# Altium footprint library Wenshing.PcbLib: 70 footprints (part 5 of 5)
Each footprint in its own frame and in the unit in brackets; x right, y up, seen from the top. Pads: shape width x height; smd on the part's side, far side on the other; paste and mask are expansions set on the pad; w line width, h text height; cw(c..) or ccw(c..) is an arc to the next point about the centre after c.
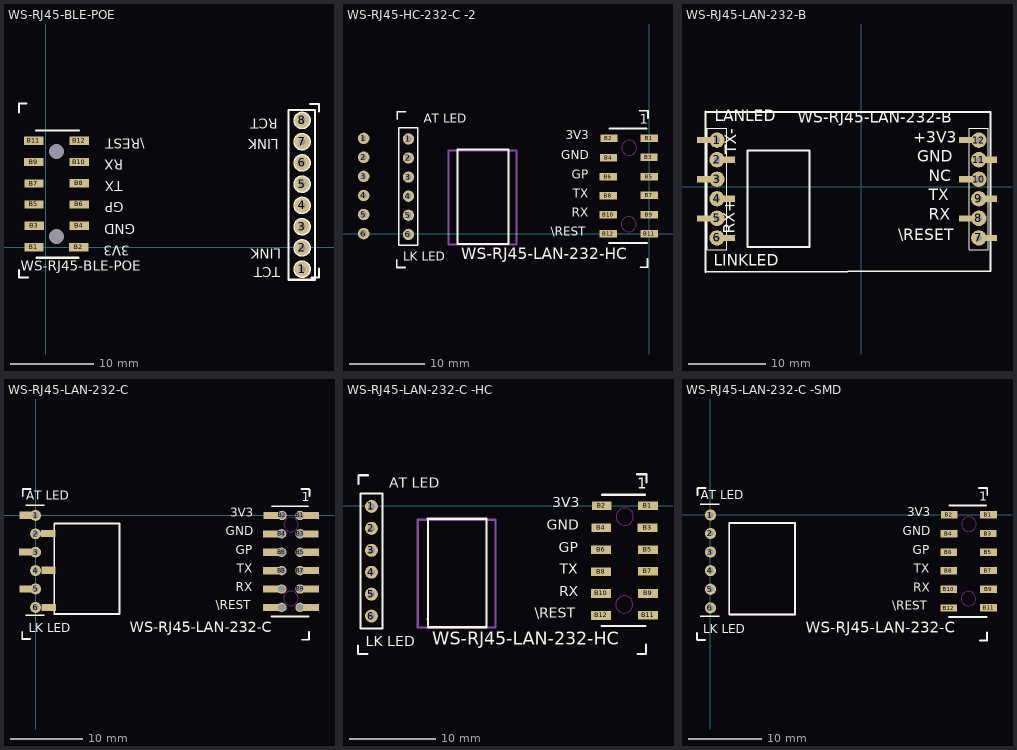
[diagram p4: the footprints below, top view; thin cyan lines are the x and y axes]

## WS-RJ45-BLE-POE [mm]
pads (23):
  round 0 hole 1.8: 0(1.241,1.272)
  round 0 hole 1.8 mask+0.102: 0(1.241,11.432)
  round 1 on Top Overlay mask+0.102: 0(1.29,6.375)
  round 1.8 hole 0.75 mask-0.3: 1(30.624,-2.635) 2(30.624,-0.095) 3(30.624,2.445) 4(30.624,4.985) 5(30.624,7.525) 6(30.624,10.065) 7(30.624,12.605) 8(30.624,15.145)
  rect 2.3x1 smd mask+0.102: B1(-1.435,0) B2(3.915,0) B3(-1.41,2.55) B4(3.965,2.575) B5(-1.435,5.1) B6(3.99,5.1) B7(-1.435,7.6) B8(3.99,7.65) B9(-1.46,10.175) B10(3.99,10.175) B11(-1.46,12.7) B12(3.99,12.725)
Top Overlay:
  circle w0.5: c30.624,-2.635 r0.8
  circle w0.5: c30.624,2.445 r0.8
  circle w0.5: c30.624,4.985 r0.8
  circle w0.5: c30.624,-0.095 r0.8
  circle w0.5: c30.624,15.145 r0.8
  circle w0.5: c30.624,7.525 r0.8
  circle w0.5: c30.624,10.065 r0.8
  circle w0.5: c30.624,12.605 r0.8
  lines w0.254: -3.226,-2.743 -3.226,-3.632 -2.159,-3.632 ; -3.226,16.104 -3.226,17.17 -2.337,17.17 ; -1.16,13.95 3.94,13.95 ; -1.11,-1.275 3.865,-1.275 ; 31.572,17.12 32.639,17.12 32.639,16.231 ; 31.75,-3.632 32.639,-3.632 32.639,-2.565 ; 28.973,-3.905 32.148,-3.905 32.148,16.415 28.973,16.415 28.973,-3.905
  text "LINK" at 28.143,0.254 h2.03
  text "RCT" at 27.737,15.773 h2.03
  text "WS-RJ45-BLE-POE" at -2.997,-3.251 h1.98
  text "TCT" at 28.016,-1.981 h2.03
  text "LINK" at 27.838,13.335 h2.03
  text "\REST" at 11.819,13.346 h2.03
  text "RX" at 9.246,10.878 h2.03
  text "TX" at 9.152,8.317 h2.03
  text "GP" at 9.279,5.777 h2.03
  text "GND" at 10.657,3.181 h2.03
  text "3V3" at 10.041,0.57 h2.03
Bottom Overlay:
  lines w0.254: 29.608,-3.905 31.513,-3.905 ; 29.608,-1.365 31.513,-1.365 ; 29.608,1.175 31.513,1.175 ; 29.608,3.715 31.513,3.715 ; 29.608,6.255 31.513,6.255 ; 29.608,8.795 31.513,8.795 ; 29.608,11.335 31.513,11.335 ; 29.608,16.415 31.513,16.415 ; 29.608,13.875 31.513,13.875 29.608,13.875
3D body "Connector 12-pin 2.54mm SMT.stp": height 6, standoff -0.2, extent -2.468,-1.299 5.182,13.741

## WS-RJ45-HC-232-C -2 [mm]
pads (25):
  round 1.524 hole 0.8 mask+0.102: 1(-38,12.675) 2(-38,10.16) 3(-38,7.62) 4(-38,5.08) 5(-38,2.54) 6(-38,0)
  round 1.5 hole 0.8 mask+0.102: 1(-32.058,12.608) 2(-32.058,10.068) 3(-32.058,7.528) 4(-32.058,4.988) 5(-32.058,2.448) 6(-32.058,-0.092)
  rect 0.2x0.2 on Bottom Overlay: 2(-32.058,6.308)
  rect 2.3x1 smd mask+0.102: B1(-0.025,12.7) B2(-5.375,12.7) B3(-0.05,10.15) B4(-5.425,10.125) B5(-0.025,7.6) B6(-5.45,7.6) B7(-0.025,5.1) B8(-5.45,5.05) B9(0,2.525) B10(-5.45,2.525) B11(0,0) B12(-5.45,-0.025)
Top Overlay:
  lines w0.203: -33.328,-1.524 -33.328,14.097 -30.788,14.097 -30.788,-1.524 -33.328,-1.524
  lines w0.254: -33.612,-3.527 -33.612,-4.475 -33.585,-4.502 -32.512,-4.502 ; -33.537,15.248 -33.537,16.196 -33.51,16.223 -32.437,16.223 ; -25.554,11.176 -18.749,11.176 ; -25.523,-0.462 -25.518,-0.457 -25.513,-0.457 ; -25.513,11.176 -25.513,-0.457 ; -18.718,11.176 -18.718,-1.397 -25.173,-1.397 -25.471,-1.397 -25.513,-1.356 -25.513,-0.457 ; -5.4,-1.25 -0.3,-1.25 ; -5.325,13.975 -0.35,13.975 ; -1.285,16.35 -0.212,16.35 -0.185,16.323 -0.185,15.375 ; -1.21,-4.475 -0.262,-4.475 -0.235,-4.448 -0.235,-3.375
  text "WS-RJ45-LAN-232-HC" at -25,-3.92 h2.54
  text "\REST" at -13.141,-0.697 h2.03
  text "RX" at -10.315,1.822 h2.03
  text "TX" at -10.22,4.383 h2.03
  text "GP" at -10.347,6.923 h2.03
  text "GND" at -11.725,9.519 h2.03
  text "3V3" at -11.109,12.13 h2.03
  text "AT LED" at -29.999,14.351 h2.03
  text "LK LED" at -32.743,-3.999 h2.03
  text "1" at -1.25,14.65 h1.27
Keep-Out Layer:
  circle w0.051: c-2.7,11.425 r1
  circle w0.051: c-2.75,1.25 r1
Mechanical 13:
  lines w0.254: -26.697,-1.422 -17.68,-1.422 -17.68,11.074 -26.621,11.074 -26.697,11.074 -26.697,-1.422
3D body "Copy of RJ45 HC多IO.step": height 9.59, standoff -1.95, extent -33.682,-4.533 2.055,16.217
3D body "Connector 12-pin 2.54mm SMT.stp": height 6.5, standoff 0.3, extent -6.75,-1.09 0.9,13.95
3D body: height 3.55, standoff 0, extent -33.3,-1.666 -30.801,14.073

## WS-RJ45-LAN-232-B [mm]
pads (48):
  rect 0.2x0.2 on Top Overlay: 0(-18.729,-6.625) 0(-18.729,-4.085) 0(-18.729,-1.545) 0(-18.729,0.995) 0(-18.729,3.535) 0(-18.729,6.075) 0(15.271,-6.625) 0(15.271,-4.085) 0(15.271,-1.545) 0(15.271,0.995) 0(15.271,3.535) 0(15.271,6.075) 1(-18.729,-0.275) 1(-18.729,-4.085) 1(-18.729,-1.545) 1(-18.729,0.995) 1(-18.729,3.535) 1(-18.729,6.075) 1(15.271,-0.275) 1(15.271,-4.085) 1(15.271,-1.545) 1(15.271,0.995) 1(15.271,3.535) 1(15.271,6.075)
  rect 2x0.8 smd: 1(-20.329,6.075) 3(-20.329,0.995) 5(-20.329,-4.085) 8(13.671,-4.085) 10(13.671,0.995) 12(13.671,6.075)
  round 2 hole 0.8 mask+0.102: 1(-18.729,6.075) 2(-18.729,3.535) 3(-18.729,0.995) 4(-18.729,-1.545) 5(-18.729,-4.085) 6(-18.729,-6.625) 7(15.271,-6.625) 8(15.271,-4.085) 9(15.271,-1.545) 10(15.271,0.995) 11(15.271,3.535) 12(15.271,6.075)
  rect 1.7x0.8 smd: 2(-17.225,3.535) 4(-17.225,-1.545) 6(-17.225,-6.625) 7(16.775,-6.625) 9(16.775,-1.545) 11(16.775,3.535)
Top Overlay:
  lines w0.1: -19.979,7.595 -18.729,7.595 -17.479,7.595 ; -19.979,7.595 -19.979,-8.145 -18.729,-8.145 -17.479,-8.145 -17.479,-0.275 -17.479,7.595 ; -19.979,7.595 -19.129,7.595 -17.479,7.595 ; 14.021,7.595 15.271,7.595 16.521,7.595 ; 14.021,7.595 14.021,-8.145 15.271,-8.145 16.521,-8.145 16.521,-0.275 16.521,7.595 ; 14.021,7.595 14.871,7.595 16.521,7.595
  lines w0.254: -20.254,9.75 16.746,9.75 ; -20.229,9.8 -20.229,-11.071 16.771,-10.921 16.771,9.7 ; -14.775,-7.775 -6.729,-7.775 -6.729,4.725 -14.775,4.725 -14.775,-7.775
  text "WS-RJ45-LAN-232-B" at -8.225,7.825 h2.54
  text "+3V3" at 6.771,5.225 h2.5
  text "GND" at 7.271,2.725 h2.5
  text "NC" at 8.771,0.225 h2.5
  text "TX" at 8.771,-2.275 h2.5
  text "RX" at 8.771,-4.775 h2.5
  text "\RESET" at 4.771,-7.475 h2.5
  text "LINKLED" at -19.129,-10.759 h2.5
  text "RX+" at -15.911,-6.06 h2.5
  text "TX-" at -15.729,4.225 h2.5
  text "LANLED" at -19.05,8.025 h2.5
Bottom Solder:
  circle w0.8: c15.271,6.075 r0.4
  circle w0.8: c15.246,3.525 r0.4
  circle w0.8: c15.296,1 r0.4
  circle w0.8: c15.271,-1.55 r0.4
  circle w0.8: c15.246,-4.075 r0.4
  circle w0.8: c15.271,-6.6 r0.4
  circle w0.8: c-18.729,6.075 r0.4
  circle w0.8: c-18.729,3.525 r0.4
  circle w0.8: c-18.729,1.025 r0.4
  circle w0.8: c-18.729,-1.575 r0.4
  circle w0.8: c-18.729,-4.1 r0.4
  circle w0.8: c-18.729,-6.6 r0.4
Mechanical 10:
  lines w0.1: -19.129,-7.025 -18.329,-7.025 -18.329,-6.225 -19.129,-6.225 -19.129,-7.025 ; -19.129,-4.485 -18.329,-4.485 -18.329,-3.685 -19.129,-3.685 -19.129,-4.485 ; -19.129,-1.945 -18.329,-1.945 -18.329,-1.145 -19.129,-1.145 -19.129,-1.945 ; -19.129,0.595 -18.329,0.595 -18.329,1.395 -19.129,1.395 -19.129,0.595 ; -19.129,3.135 -18.329,3.135 -18.329,3.935 -19.129,3.935 -19.129,3.135 ; -19.129,5.675 -18.329,5.675 -18.329,6.475 -19.129,6.475 -19.129,5.675 ; 14.871,-7.025 15.671,-7.025 15.671,-6.225 14.871,-6.225 14.871,-7.025 ; 14.871,-4.485 15.671,-4.485 15.671,-3.685 14.871,-3.685 14.871,-4.485 ; 14.871,-1.945 15.671,-1.945 15.671,-1.145 14.871,-1.145 14.871,-1.945 ; 14.871,0.595 15.671,0.595 15.671,1.395 14.871,1.395 14.871,0.595 ; 14.871,3.135 15.671,3.135 15.671,3.935 14.871,3.935 14.871,3.135 ; 14.871,5.675 15.671,5.675 15.671,6.475 14.871,6.475 14.871,5.675
3D body: height 0.2, standoff 0, extent -17.499,3.135 -16.6,3.935
3D body: height 0.2, standoff 0, extent -17.499,-1.945 -16.6,-1.145
3D body: height 0.2, standoff 0, extent -17.499,-7.025 -16.6,-6.225
3D body: height 0.2, standoff 0, extent -20.859,5.675 -19.959,6.475
3D body: height 0.2, standoff 0, extent -20.859,0.595 -19.959,1.395
3D body: height 0.2, standoff 0, extent -20.859,-4.485 -19.959,-3.685
3D body: height 0.3, standoff 0, extent -19.129,5.676 -18.33,6.474
3D body: height 0.3, standoff 0, extent -19.129,3.136 -18.33,3.934
3D body: height 0.3, standoff 0, extent -19.129,0.596 -18.33,1.394
3D body: height 0.3, standoff 0, extent -19.129,-1.944 -18.33,-1.146
3D body: height 0.3, standoff 0, extent -19.129,-4.484 -18.33,-3.686
3D body: height 0.3, standoff 0, extent -19.129,-7.024 -18.33,-6.226
3D body: height 3.55, standoff 0, extent -19.979,-8.144 -17.48,7.594
3D body: height 0.2, standoff 0, extent 16.501,3.135 17.4,3.935
3D body: height 0.2, standoff 0, extent 16.501,-1.945 17.4,-1.145
3D body: height 0.2, standoff 0, extent 16.501,-7.025 17.4,-6.225
3D body: height 0.2, standoff 0, extent 14.812,5.351 15.712,6.151
3D body: height 0.2, standoff 0, extent 14.558,0.525 15.458,1.325
3D body: height 0.2, standoff 0, extent 14.685,-4.682 15.585,-3.882
3D body: height 0.3, standoff 0, extent 14.871,5.676 15.67,6.474
3D body: height 0.3, standoff 0, extent 14.871,3.136 15.67,3.934
3D body: height 0.3, standoff 0, extent 14.871,0.596 15.67,1.394
3D body: height 0.3, standoff 0, extent 14.871,-1.944 15.67,-1.146
3D body: height 0.3, standoff 0, extent 14.871,-4.484 15.67,-3.686
3D body: height 0.3, standoff 0, extent 14.871,-7.024 15.67,-6.226
3D body: height 3.55, standoff 0, extent 14.021,-8.144 16.52,7.594
3D body "TRW-TCP232.step": height 9.09, standoff -2.45, extent -20.426,-11 16.826,9.75

## WS-RJ45-LAN-232-C [mm]
pads (38):
  round 1 on Top Overlay mask+0.102: 0(-0.025,-6.35) 0(35.25,-6.375)
  rect 2x1 smd mask+0.102: 1(-1.21,0.025) 2(1.765,-2.5) 3(-1.285,-5.05) 4(1.79,-7.575) 5(-1.21,-10.15) 6(1.815,-12.7)
  round 1.5 hole 0.8 mask+0.102: 1(0,0) 2(0,-2.54) 3(0,-5.08) 4(0,-7.62) 5(0,-10.16) 6(0,-12.7)
  round 1.3 hole 1 mask+0.102: B1(36.54,0) B2(34.04,0) B3(36.54,-2.54) B4(34,-2.54) B5(36.54,-5.08) B6(34,-5.08) B7(36.54,-7.62) B8(34,-7.62) B9(36.54,-10.16) B10(34,-10.16) B11(36.54,-12.7) B12(34,-12.7)
  rect 2.3x1 smd mask+0.102: B1(37.975,0) B2(32.625,0) B3(37.95,-2.55) B4(32.575,-2.575) B5(37.975,-5.1) B6(32.55,-5.1) B7(37.975,-7.6) B8(32.55,-7.65) B9(38,-10.175) B10(32.55,-10.175) B11(38,-12.7) B12(32.55,-12.725)
Top Layer:
  lines w0.305: 0,-10.16 0.045,-10.115 ; 0,-7.62 0.229,-7.849
Top Overlay:
  lines w0.203: -1.365,-13.82 1.175,-13.82 ; -1.365,1.42 1.175,1.42
  lines w0.254: -1.835,-16.1 -1.835,-17.048 -1.808,-17.075 -0.735,-17.075 ; -1.76,2.675 -1.76,3.623 -1.733,3.65 -0.66,3.65 ; 32.6,-13.95 37.7,-13.95 ; 32.675,1.275 37.65,1.275 ; 36.715,3.65 37.788,3.65 37.815,3.623 37.815,2.675 ; 36.79,-17.175 37.738,-17.175 37.765,-17.148 37.765,-16.075 ; 2.575,-13.595 11.575,-13.595 11.575,-1.095 2.575,-1.095 2.575,-13.595
  text "1" at 36.75,1.95 h1.27
  text "LK LED" at -0.966,-16.572 h2.03
  text "AT LED" at -1.31,1.725 h2.03
  text "3V3" at 26.891,-0.57 h2.03
  text "GND" at 26.275,-3.181 h2.03
  text "GP" at 27.653,-5.777 h2.03
  text "TX" at 27.78,-8.317 h2.03
  text "RX" at 27.685,-10.878 h2.03
  text "\REST" at 24.859,-13.397 h2.03
  text "WS-RJ45-LAN-232-C" at 13,-16.62 h2.54
Bottom Overlay:
  circle w0.4: c34.05,0 r1.2
  circle w0.4: c36.54,0 r1.2
  circle w0.4: c36.54,-2.54 r1.2
  circle w0.4: c34,-2.54 r1.2
  circle w0.4: c34,-5.08 r1.2
  circle w0.4: c36.54,-5.08 r1.2
  circle w0.4: c36.54,-7.62 r1.2
  circle w0.4: c34,-7.62 r1.2
  circle w0.4: c36.54,-10.16 r1.2
  circle w0.4: c34,-10.16 r1.2
  circle w0.4: c34,-12.7 r1.2
  circle w0.4: c36.54,-12.7 r1.2
  circle w0.4: c0,0 r1.2
  circle w0.4: c0,-2.54 r1.2
  circle w0.4: c0,-5.08 r1.2
  circle w0.4: c0,-7.62 r1.2
  circle w0.4: c0,-10.16 r1.2
  circle w0.4: c0,-12.7 r1.2
Keep-Out Layer:
  circle w0.051: c35.25,-11.45 r1
  circle w0.051: c35.3,-1.275 r1
3D body "Connector 12-pin 2.54mm SMT.stp": height 6.5, standoff 0.3, extent 31.25,-13.79 38.9,1.25
3D body "RJ45 LNA多IO.step": height 9.27, standoff -2.95, extent -1.799,-17.375 37.749,3.375
3D body: height 3.55, standoff 0, extent -1.199,-13.844 1.299,1.894

## WS-RJ45-LAN-232-C -HC [mm]
pads (19):
  round 1.5 hole 0.8 mask+0.102: 1(5.942,-0.092) 2(5.942,-2.632) 3(5.942,-5.172) 4(5.942,-7.712) 5(5.942,-10.252) 6(5.942,-12.792)
  rect 0.2x0.2 on Bottom Overlay: 2(5.942,-6.392)
  rect 2.3x1 smd mask+0.102: B1(37.975,0) B2(32.625,0) B3(37.95,-2.55) B4(32.575,-2.575) B5(37.975,-5.1) B6(32.55,-5.1) B7(37.975,-7.6) B8(32.55,-7.65) B9(38,-10.175) B10(32.55,-10.175) B11(38,-12.7) B12(32.55,-12.725)
Top Overlay:
  lines w0.203: 4.672,-14.224 4.672,1.397 7.212,1.397 7.212,-14.224 4.672,-14.224
  lines w0.254: 4.388,-16.227 4.388,-17.175 4.415,-17.202 5.488,-17.202 ; 4.463,2.548 4.463,3.496 4.49,3.523 5.563,3.523 ; 12.446,-1.524 19.251,-1.524 ; 12.477,-13.162 12.482,-13.157 12.487,-13.157 ; 12.487,-1.524 12.487,-13.157 ; 19.282,-1.524 19.282,-14.097 12.827,-14.097 12.529,-14.097 12.487,-14.056 12.487,-13.157 ; 32.6,-13.95 37.7,-13.95 ; 32.675,1.275 37.65,1.275 ; 36.715,3.65 37.788,3.65 37.815,3.623 37.815,2.675 ; 36.79,-17.175 37.738,-17.175 37.765,-17.148 37.765,-16.075
  text "WS-RJ45-LAN-232-HC" at 13,-16.62 h2.54
  text "\REST" at 24.859,-13.397 h2.03
  text "RX" at 27.685,-10.878 h2.03
  text "TX" at 27.78,-8.317 h2.03
  text "GP" at 27.653,-5.777 h2.03
  text "GND" at 26.275,-3.181 h2.03
  text "3V3" at 26.891,-0.57 h2.03
  text "AT LED" at 8.001,1.651 h2.03
  text "LK LED" at 5.257,-16.699 h2.03
  text "1" at 36.75,1.95 h1.27
Keep-Out Layer:
  circle w0.051: c35.3,-1.275 r1
  circle w0.051: c35.25,-11.45 r1
Mechanical 13:
  lines w0.254: 11.303,-14.122 20.32,-14.122 20.32,-1.626 11.379,-1.626 11.303,-1.626 11.303,-14.122
3D body "Copy of RJ45 HC多IO.step": height 9.59, standoff -1.95, extent 4.318,-17.233 40.055,3.517
3D body "Connector 12-pin 2.54mm SMT.stp": height 6.5, standoff 0.3, extent 31.25,-13.79 38.9,1.25
3D body: height 3.55, standoff 0, extent 4.7,-14.366 7.199,1.373

## WS-RJ45-LAN-232-C -SMD [mm]
pads (18):
  round 1.524 hole 0.8 mask+0.102: 1(0,-0.025) 2(0,-2.54) 3(0,-5.08) 4(0,-7.62) 5(0,-10.16) 6(0,-12.7)
  rect 2.3x1 smd mask+0.102: B1(37.975,0) B2(32.625,0) B3(37.95,-2.55) B4(32.575,-2.575) B5(37.975,-5.1) B6(32.55,-5.1) B7(37.975,-7.6) B8(32.55,-7.65) B9(38,-10.175) B10(32.55,-10.175) B11(38,-12.7) B12(32.55,-12.725)
Top Overlay:
  lines w0.203: -1.365,-13.82 1.175,-13.82 ; -1.365,1.42 1.175,1.42
  lines w0.254: -1.835,-16.1 -1.835,-17.048 -1.808,-17.075 -0.735,-17.075 ; -1.76,2.675 -1.76,3.623 -1.733,3.65 -0.66,3.65 ; 32.6,-13.95 37.7,-13.95 ; 32.675,1.275 37.65,1.275 ; 36.715,3.65 37.788,3.65 37.815,3.623 37.815,2.675 ; 36.79,-17.175 37.738,-17.175 37.765,-17.148 37.765,-16.075 ; 2.575,-13.595 11.575,-13.595 11.575,-1.095 2.575,-1.095 2.575,-13.595
  text "1" at 36.75,1.95 h1.27
  text "LK LED" at -0.966,-16.572 h2.03
  text "AT LED" at -1.31,1.725 h2.03
  text "3V3" at 26.891,-0.57 h2.03
  text "GND" at 26.275,-3.181 h2.03
  text "GP" at 27.653,-5.777 h2.03
  text "TX" at 27.78,-8.317 h2.03
  text "RX" at 27.685,-10.878 h2.03
  text "\REST" at 24.859,-13.397 h2.03
  text "WS-RJ45-LAN-232-C" at 13,-16.62 h2.54
Keep-Out Layer:
  circle w0.051: c35.25,-11.45 r1
  circle w0.051: c35.3,-1.275 r1
Mechanical 13:
  lines w0.254: 2.565,-13.614 2.565,-1.118 2.642,-1.118 11.582,-1.118 11.582,-13.614 2.565,-13.614
3D body "Connector 12-pin 2.54mm SMT.stp": height 6.5, standoff 0.3, extent 31.25,-13.79 38.9,1.25
3D body "RJ45 LNA多IO.step": height 9.27, standoff -2.95, extent -1.799,-17.375 37.749,3.375
3D body: height 3.55, standoff 0, extent -1.199,-13.844 1.299,1.894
